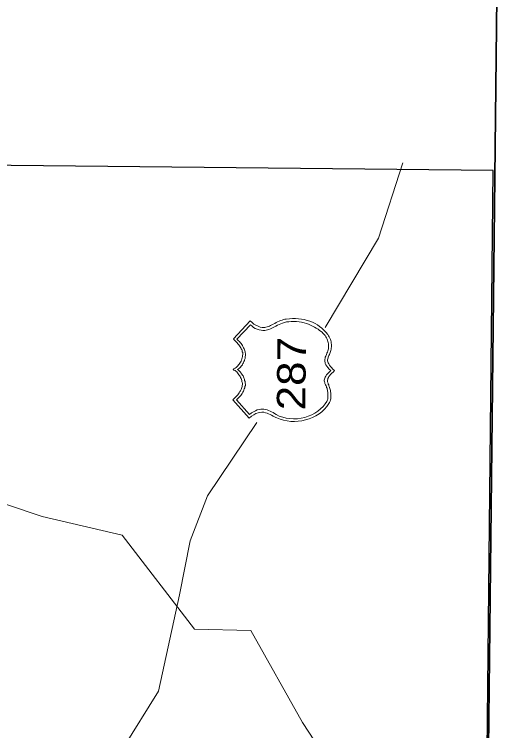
# Model space of a CAD drawing. Extents: x 2356576 to 2377878, y 6966390 to 6990634.
# Drawn here: x 2366109.4 to 2366226.3, y 6969120 to 6969290.7 of the extents above; entities that cross this region are included whole.
import ezdxf

# ---------------------------------------------------------------- set-up
doc = ezdxf.new("R2010")
doc.units = 0
doc.header["$LTSCALE"] = 7.1
doc.layers.add('19', color=7, linetype='Continuous', lineweight=13)
doc.layers.add('8', color=7, linetype='Continuous', lineweight=13)

msp = doc.modelspace()

# ---------------------------------------------------------------- linework, layer by layer
at = {"layer": '19', "lineweight": 35}
msp.add_line((2366217.375, 6968654.072), (2366226.339, 6969461.286), dxfattribs=at)
at = {"layer": '19'}
for p, q in [((2366202.034, 6969255.279), (2366196.264, 6969237.31)), ((2366196.264, 6969237.31), (2366183.535, 6969216.049)), ((2366155.514, 6969175.953), (2366167.219, 6969193.417))]:
    msp.add_line(p, q, dxfattribs=at)
at = {"layer": '19', "lineweight": 25}
msp.add_lwpolyline([(2365597.072, 6968660.498), (2366217.375, 6968654.072), (2366223.585, 6969253.468), (2365603.282, 6969259.894)], dxfattribs=at)
at = {"layer": '19'}
for points in [[(2366165.458, 6969194.423), (2366161.515, 6969198.816), (2366161.758, 6969199.053), (2366162.028, 6969199.291), (2366162.243, 6969199.556), (2366162.485, 6969199.766), (2366162.696, 6969200.032), (2366162.878, 6969200.27), (2366163.061, 6969200.508), (2366163.243, 6969200.778), (2366163.366, 6969200.985), (2366163.488, 6969201.256), (2366163.611, 6969201.494), (2366163.674, 6969201.762), (2366163.736, 6969202.001), (2366163.798, 6969202.212), (2366163.801, 6969202.512), (2366163.804, 6969202.78), (2366163.746, 6969202.961), (2366163.688, 6969203.174), (2366163.663, 6969203.414), (2366163.573, 6969203.655), (2366163.488, 6969203.896), (2366163.37, 6969204.105), (2366163.28, 6969204.346), (2366163.163, 6969204.587), (2366162.985, 6969204.801), (2366162.808, 6969205.043), (2366162.63, 6969205.253), (2366162.484, 6969205.466), (2366162.274, 6969205.616), (2366162.067, 6969205.799), (2366161.796, 6969205.893), (2366161.59, 6969206.043), (2366161.799, 6969206.193), (2366162.073, 6969206.339), (2366162.315, 6969206.516), (2366162.497, 6969206.694), (2366162.707, 6969206.904), (2366162.889, 6969207.142), (2366163.044, 6969207.349), (2366163.194, 6969207.587), (2366163.348, 6969207.825), (2366163.499, 6969208.036), (2366163.562, 6969208.335), (2366163.684, 6969208.542), (2366163.747, 6969208.873), (2366163.81, 6969209.081), (2366163.873, 6969209.38), (2366163.907, 6969209.62), (2366163.909, 6969209.832), (2366163.88, 6969210.1), (2366163.794, 6969210.281), (2366163.737, 6969210.554), (2366163.647, 6969210.794), (2366163.529, 6969211.004), (2366163.412, 6969211.217), (2366163.266, 6969211.486), (2366163.089, 6969211.7), (2366162.939, 6969211.942), (2366162.733, 6969212.152), (2366162.556, 6969212.426), (2366162.346, 6969212.636), (2366162.109, 6969212.878), (2366161.871, 6969213.093), (2366161.665, 6969213.335), (2366165.698, 6969217.642), (2366166.114, 6969217.249), (2366166.53, 6969216.853), (2366167.039, 6969216.58), (2366167.577, 6969216.362), (2366168.083, 6969216.149), (2366168.534, 6969216.052), (2366168.922, 6969216.048), (2366169.194, 6969216.045), (2366169.435, 6969216.103), (2366169.703, 6969216.192), (2366169.944, 6969216.278), (2366170.246, 6969216.394), (2366170.547, 6969216.543), (2366170.849, 6969216.688), (2366171.183, 6969216.865), (2366171.512, 6969217.041), (2366171.874, 6969217.218), (2366172.208, 6969217.394), (2366172.598, 6969217.542), (2366172.931, 6969217.687), (2366173.26, 6969217.803), (2366173.594, 6969217.92), (2366173.955, 6969218.008), (2366174.283, 6969218.065), (2366175.036, 6969218.145), (2366175.785, 6969218.229), (2366176.477, 6969218.222), (2366177.196, 6969218.122), (2366177.915, 6969218.055), (2366178.574, 6969217.928), (2366179.232, 6969217.741), (2366179.89, 6969217.527), (2366180.516, 6969217.308), (2366181.144, 6969217.002)], [(2366182.148, 6969215.403), (2366181.851, 6969215.674), (2366181.433, 6969215.918), (2366181.016, 6969216.163), (2366180.566, 6969216.407), (2366180.089, 6969216.624), (2366179.583, 6969216.838), (2366179.073, 6969217.023), (2366178.506, 6969217.181), (2366177.908, 6969217.335), (2366177.336, 6969217.401), (2366176.709, 6969217.499), (2366176.077, 6969217.506), (2366175.417, 6969217.481), (2366174.849, 6969217.427), (2366174.308, 6969217.372), (2366173.854, 6969217.229), (2366173.373, 6969217.114), (2366172.951, 6969216.938), (2366172.562, 6969216.79), (2366172.168, 6969216.614), (2366171.806, 6969216.41), (2366171.444, 6969216.202), (2366171.142, 6969216.025), (2366170.812, 6969215.88), (2366170.479, 6969215.732), (2366170.117, 6969215.588), (2366169.816, 6969215.499), (2366169.487, 6969215.414), (2366169.127, 6969215.358), (2366168.707, 6969215.33), (2366168.255, 6969215.427), (2366167.808, 6969215.52), (2366167.358, 6969215.644), (2366166.88, 6969215.829), (2366166.494, 6969216.073), (2366166.105, 6969216.377), (2366165.72, 6969216.681), (2366162.473, 6969213.295), (2366162.683, 6969213.085), (2366162.889, 6969212.902), (2366163.127, 6969212.688), (2366163.305, 6969212.478), (2366163.514, 6969212.236), (2366163.66, 6969211.994), (2366163.809, 6969211.753), (2366163.955, 6969211.511), (2366164.104, 6969211.238), (2366164.249, 6969210.996), (2366164.339, 6969210.727), (2366164.396, 6969210.487), (2366164.482, 6969210.246), (2366164.511, 6969210.033), (2366164.537, 6969209.825), (2366164.567, 6969209.613), (2366164.533, 6969209.405), (2366164.502, 6969209.165), (2366164.5, 6969208.894), (2366164.437, 6969208.686), (2366164.342, 6969208.387), (2366164.28, 6969208.176), (2366164.19, 6969207.937), (2366164.067, 6969207.67), (2366163.945, 6969207.459), (2366163.822, 6969207.192), (2366163.668, 6969207.014), (2366163.486, 6969206.804), (2366163.335, 6969206.565), (2366163.122, 6969206.388), (2366162.912, 6969206.21), (2366162.67, 6969206.032), (2366162.876, 6969205.85), (2366163.114, 6969205.668), (2366163.264, 6969205.486), (2366163.442, 6969205.304), (2366163.56, 6969205.095), (2366163.707, 6969204.942), (2366163.856, 6969204.7), (2366163.974, 6969204.519), (2366164.06, 6969204.31), (2366164.178, 6969204.069), (2366164.236, 6969203.888), (2366164.293, 6969203.647), (2366164.351, 6969203.435), (2366164.441, 6969203.226), (2366164.438, 6969202.986), (2366164.496, 6969202.773), (2366164.522, 6969202.565), (2366164.519, 6969202.265), (2366164.428, 6969201.994), (2366164.393, 6969201.694), (2366164.271, 6969201.455), (2366164.179, 6969201.156), (2366164.056, 6969200.858), (2366163.902, 6969200.651), (2366163.751, 6969200.353), (2366163.568, 6969200.083), (2366163.414, 6969199.844), (2366163.172, 6969199.639), (2366162.989, 6969199.369), (2366162.747, 6969199.163)], [(2366181.144, 6969217.002), (2366181.709, 6969216.668), (2366182.217, 6969216.27), (2366182.781, 6969215.905), (2366183.256, 6969215.392), (2366183.731, 6969214.935), (2366184.146, 6969214.39), (2366184.354, 6969214.088), (2366184.532, 6969213.818), (2366184.677, 6969213.517), (2366184.793, 6969213.216), (2366184.911, 6969212.942), (2366184.94, 6969212.642), (2366184.996, 6969212.313), (2366185.053, 6969212.041), (2366185.05, 6969211.713), (2366185.047, 6969211.413), (2366185.012, 6969211.141), (2366184.982, 6969210.901), (2366184.886, 6969210.602), (2366184.824, 6969210.363), (2366184.761, 6969210.124), (2366184.639, 6969209.885), (2366184.548, 6969209.646), (2366184.454, 6969209.407), (2366184.364, 6969209.228), (2366184.27, 6969208.989), (2366184.24, 6969208.809), (2366184.177, 6969208.57), (2366184.115, 6969208.33), (2366184.141, 6969208.122), (2366184.198, 6969207.881), (2366184.287, 6969207.608), (2366184.433, 6969207.367), (2366184.582, 6969207.097), (2366184.787, 6969206.795), (2366185.056, 6969206.492), (2366185.412, 6969206.157), (2366185.797, 6969205.793), (2366185.433, 6969205.436), (2366185.13, 6969205.14), (2366184.827, 6969204.875), (2366184.616, 6969204.577), (2366184.434, 6969204.367), (2366184.311, 6969204.128), (2366184.217, 6969203.921), (2366184.155, 6969203.71), (2366184.125, 6969203.53), (2366184.123, 6969203.322), (2366184.121, 6969203.142), (2366184.179, 6969202.929), (2366184.237, 6969202.781), (2366184.263, 6969202.568), (2366184.381, 6969202.359), (2366184.439, 6969202.179), (2366184.529, 6969201.998), (2366184.587, 6969201.785), (2366184.673, 6969201.544), (2366184.73, 6969201.276), (2366184.787, 6969201.035), (2366184.816, 6969200.763), (2366184.874, 6969200.494), (2366184.931, 6969200.253), (2366184.928, 6969199.953), (2366184.925, 6969199.681), (2366184.922, 6969199.413), (2366184.859, 6969199.082), (2366184.796, 6969198.815), (2366184.701, 6969198.516), (2366184.578, 6969198.217), (2366184.427, 6969197.918), (2366183.968, 6969197.231), (2366183.393, 6969196.577), (2366182.787, 6969195.955), (2366182.089, 6969195.451), (2366181.336, 6969194.978), (2366180.552, 6969194.598), (2366179.737, 6969194.307), (2366178.867, 6969194.044), (2366177.992, 6969193.845), (2366177.123, 6969193.734), (2366176.223, 6969193.683), (2366175.351, 6969193.692), (2366174.484, 6969193.789), (2366173.645, 6969193.95), (2366172.808, 6969194.199), (2366172.059, 6969194.506), (2366171.76, 6969194.63), (2366171.434, 6969194.781), (2366171.136, 6969194.964), (2366170.778, 6969195.148), (2366170.419, 6969195.331), (2366170.061, 6969195.515), (2366169.703, 6969195.671), (2366169.312, 6969195.763), (2366168.893, 6969195.859), (2366168.445, 6969195.864), (2366167.993, 6969195.837), (2366167.543, 6969195.721), (2366167.029, 6969195.547), (2366166.519, 6969195.284)], [(2366162.383, 6969198.807), (2366165.499, 6969195.354), (2366165.983, 6969195.709), (2366166.466, 6969196.004), (2366166.916, 6969196.208), (2366167.338, 6969196.415), (2366167.791, 6969196.499), (2366168.18, 6969196.587), (2366168.541, 6969196.611), (2366168.96, 6969196.579), (2366169.351, 6969196.483), (2366169.711, 6969196.419), (2366170.069, 6969196.295), (2366170.428, 6969196.111), (2366170.786, 6969195.96), (2366171.144, 6969195.776), (2366171.47, 6969195.561), (2366171.828, 6969195.349), (2366172.604, 6969194.949), (2366173.441, 6969194.672), (2366174.251, 6969194.452), (2366175.15, 6969194.354), (2366176.017, 6969194.313), (2366176.917, 6969194.336), (2366177.819, 6969194.475), (2366178.661, 6969194.646), (2366179.504, 6969194.909), (2366180.347, 6969195.261), (2366181.104, 6969195.673), (2366181.828, 6969196.113), (2366182.462, 6969196.647), (2366183.068, 6969197.213), (2366183.554, 6969197.836), (2366183.981, 6969198.463), (2366184.042, 6969198.611), (2366184.136, 6969198.79), (2366184.166, 6969199.001), (2366184.169, 6969199.241), (2366184.203, 6969199.421), (2366184.205, 6969199.661), (2366184.208, 6969199.901), (2366184.21, 6969200.141), (2366184.181, 6969200.409), (2366184.183, 6969200.621), (2366184.126, 6969200.89), (2366184.1, 6969201.13), (2366184.042, 6969201.343), (2366183.985, 6969201.583), (2366183.895, 6969201.792), (2366183.869, 6969201.972), (2366183.751, 6969202.154), (2366183.661, 6969202.367), (2366183.575, 6969202.516), (2366183.485, 6969202.729), (2366183.427, 6969202.937), (2366183.401, 6969203.117), (2366183.343, 6969203.33), (2366183.345, 6969203.538), (2366183.407, 6969203.749), (2366183.47, 6969204.017), (2366183.533, 6969204.256), (2366183.715, 6969204.494), (2366183.898, 6969204.792), (2366184.201, 6969205.089), (2366184.505, 6969205.446), (2366184.868, 6969205.774), (2366184.48, 6969206.166), (2366184.156, 6969206.53), (2366183.92, 6969206.864), (2366183.711, 6969207.194), (2366183.566, 6969207.468), (2366183.509, 6969207.737), (2366183.451, 6969207.977), (2366183.454, 6969208.277), (2366183.456, 6969208.489), (2366183.519, 6969208.696), (2366183.581, 6969208.968), (2366183.672, 6969209.207), (2366183.794, 6969209.414), (2366183.889, 6969209.653), (2366183.979, 6969209.924), (2366184.102, 6969210.191), (2366184.197, 6969210.462), (2366184.288, 6969210.729), (2366184.322, 6969211), (2366184.326, 6969211.3), (2366184.356, 6969211.568), (2366184.331, 6969211.868), (2366184.334, 6969212.14), (2366184.277, 6969212.441), (2366184.221, 6969212.741), (2366184.131, 6969213.01), (2366183.986, 6969213.312), (2366183.869, 6969213.585), (2366183.692, 6969213.855), (2366183.515, 6969214.157), (2366183.278, 6969214.399), (2366183.008, 6969214.674), (2366182.803, 6969214.916), (2366182.473, 6969215.16), (2366182.148, 6969215.403)], [(2366057.323, 6969199.743), (2366069.126, 6969192.209), (2366091.194, 6969179.379), (2366116.101, 6969171.021), (2366135.168, 6969166.623), (2366152.425, 6969144.183), (2366165.834, 6969143.864), (2366178.148, 6969121.955), (2366189.725, 6969104.283), (2366199.135, 6969082.764), (2366204.465, 6969052.823), (2366210.021, 6969027.324), (2366216.934, 6968999.531), (2366220.78, 6968982.778)], [(2366162.747, 6969199.163), (2366162.565, 6969198.985), (2366162.383, 6969198.807)], [(2366166.519, 6969195.284), (2366166.003, 6969194.929), (2366165.458, 6969194.423)], [(2366155.514, 6969175.953), (2366151.383, 6969165.227), (2366148.79, 6969152.413), (2366143.811, 6969129.392), (2366135.33, 6969115.799), (2366129.355, 6969106.648), (2366121.344, 6969094.85), (2366108.711, 6969083.249), (2366095.035, 6969075.202), (2366079.714, 6969067.44), (2366061.538, 6969056.344), (2366050.004, 6969046.563), (2366038.586, 6969039.093), (2366024.252, 6969030.869), (2366017.685, 6969025.629), (2366000.609, 6969016.381)]]:
    msp.add_lwpolyline(points, dxfattribs=at)
at = {"layer": '8', "lineweight": 35}
msp.add_line((2366217.375, 6968654.072), (2366226.339, 6969461.286), dxfattribs=at)
at = {"layer": '8'}
for p, q in [((2366202.034, 6969255.279), (2366196.264, 6969237.31)), ((2366196.264, 6969237.31), (2366183.535, 6969216.049)), ((2366155.514, 6969175.953), (2366167.219, 6969193.417))]:
    msp.add_line(p, q, dxfattribs=at)
at = {"layer": '8', "lineweight": 25}
msp.add_lwpolyline([(2365597.072, 6968660.498), (2366217.375, 6968654.072), (2366223.585, 6969253.468), (2365603.282, 6969259.894)], dxfattribs=at)
at = {"layer": '8'}
for points in [[(2366165.458, 6969194.423), (2366161.515, 6969198.816), (2366161.758, 6969199.053), (2366162.028, 6969199.291), (2366162.243, 6969199.556), (2366162.485, 6969199.766), (2366162.696, 6969200.032), (2366162.878, 6969200.27), (2366163.061, 6969200.508), (2366163.243, 6969200.778), (2366163.366, 6969200.985), (2366163.488, 6969201.256), (2366163.611, 6969201.494), (2366163.674, 6969201.762), (2366163.736, 6969202.001), (2366163.798, 6969202.212), (2366163.801, 6969202.512), (2366163.804, 6969202.78), (2366163.746, 6969202.961), (2366163.688, 6969203.174), (2366163.663, 6969203.414), (2366163.573, 6969203.655), (2366163.488, 6969203.896), (2366163.37, 6969204.105), (2366163.28, 6969204.346), (2366163.163, 6969204.587), (2366162.985, 6969204.801), (2366162.808, 6969205.043), (2366162.63, 6969205.253), (2366162.484, 6969205.466), (2366162.274, 6969205.616), (2366162.067, 6969205.799), (2366161.796, 6969205.893), (2366161.59, 6969206.043), (2366161.799, 6969206.193), (2366162.073, 6969206.339), (2366162.315, 6969206.516), (2366162.497, 6969206.694), (2366162.707, 6969206.904), (2366162.889, 6969207.142), (2366163.044, 6969207.349), (2366163.194, 6969207.587), (2366163.348, 6969207.825), (2366163.499, 6969208.036), (2366163.562, 6969208.335), (2366163.684, 6969208.542), (2366163.747, 6969208.873), (2366163.81, 6969209.081), (2366163.873, 6969209.38), (2366163.907, 6969209.62), (2366163.909, 6969209.832), (2366163.88, 6969210.1), (2366163.794, 6969210.281), (2366163.737, 6969210.554), (2366163.647, 6969210.794), (2366163.529, 6969211.004), (2366163.412, 6969211.217), (2366163.266, 6969211.486), (2366163.089, 6969211.7), (2366162.939, 6969211.942), (2366162.733, 6969212.152), (2366162.556, 6969212.426), (2366162.346, 6969212.636), (2366162.109, 6969212.878), (2366161.871, 6969213.093), (2366161.665, 6969213.335), (2366165.698, 6969217.642), (2366166.114, 6969217.249), (2366166.53, 6969216.853), (2366167.039, 6969216.58), (2366167.577, 6969216.362), (2366168.083, 6969216.149), (2366168.534, 6969216.052), (2366168.922, 6969216.048), (2366169.194, 6969216.045), (2366169.435, 6969216.103), (2366169.703, 6969216.192), (2366169.944, 6969216.278), (2366170.246, 6969216.394), (2366170.547, 6969216.543), (2366170.849, 6969216.688), (2366171.183, 6969216.865), (2366171.512, 6969217.041), (2366171.874, 6969217.218), (2366172.208, 6969217.394), (2366172.598, 6969217.542), (2366172.931, 6969217.687), (2366173.26, 6969217.803), (2366173.594, 6969217.92), (2366173.955, 6969218.008), (2366174.283, 6969218.065), (2366175.036, 6969218.145), (2366175.785, 6969218.229), (2366176.477, 6969218.222), (2366177.196, 6969218.122), (2366177.915, 6969218.055), (2366178.574, 6969217.928), (2366179.232, 6969217.741), (2366179.89, 6969217.527), (2366180.516, 6969217.308), (2366181.144, 6969217.002)], [(2366182.148, 6969215.403), (2366181.851, 6969215.674), (2366181.433, 6969215.918), (2366181.016, 6969216.163), (2366180.566, 6969216.407), (2366180.089, 6969216.624), (2366179.583, 6969216.838), (2366179.073, 6969217.023), (2366178.506, 6969217.181), (2366177.908, 6969217.335), (2366177.336, 6969217.401), (2366176.709, 6969217.499), (2366176.077, 6969217.506), (2366175.417, 6969217.481), (2366174.849, 6969217.427), (2366174.308, 6969217.372), (2366173.854, 6969217.229), (2366173.373, 6969217.114), (2366172.951, 6969216.938), (2366172.562, 6969216.79), (2366172.168, 6969216.614), (2366171.806, 6969216.41), (2366171.444, 6969216.202), (2366171.142, 6969216.025), (2366170.812, 6969215.88), (2366170.479, 6969215.732), (2366170.117, 6969215.588), (2366169.816, 6969215.499), (2366169.487, 6969215.414), (2366169.127, 6969215.358), (2366168.707, 6969215.33), (2366168.255, 6969215.427), (2366167.808, 6969215.52), (2366167.358, 6969215.644), (2366166.88, 6969215.829), (2366166.494, 6969216.073), (2366166.105, 6969216.377), (2366165.72, 6969216.681), (2366162.473, 6969213.295), (2366162.683, 6969213.085), (2366162.889, 6969212.902), (2366163.127, 6969212.688), (2366163.305, 6969212.478), (2366163.514, 6969212.236), (2366163.66, 6969211.994), (2366163.809, 6969211.753), (2366163.955, 6969211.511), (2366164.104, 6969211.238), (2366164.249, 6969210.996), (2366164.339, 6969210.727), (2366164.396, 6969210.487), (2366164.482, 6969210.246), (2366164.511, 6969210.033), (2366164.537, 6969209.825), (2366164.567, 6969209.613), (2366164.533, 6969209.405), (2366164.502, 6969209.165), (2366164.5, 6969208.894), (2366164.437, 6969208.686), (2366164.342, 6969208.387), (2366164.28, 6969208.176), (2366164.19, 6969207.937), (2366164.067, 6969207.67), (2366163.945, 6969207.459), (2366163.822, 6969207.192), (2366163.668, 6969207.014), (2366163.486, 6969206.804), (2366163.335, 6969206.565), (2366163.122, 6969206.388), (2366162.912, 6969206.21), (2366162.67, 6969206.032), (2366162.876, 6969205.85), (2366163.114, 6969205.668), (2366163.264, 6969205.486), (2366163.442, 6969205.304), (2366163.56, 6969205.095), (2366163.707, 6969204.942), (2366163.856, 6969204.7), (2366163.974, 6969204.519), (2366164.06, 6969204.31), (2366164.178, 6969204.069), (2366164.236, 6969203.888), (2366164.293, 6969203.647), (2366164.351, 6969203.435), (2366164.441, 6969203.226), (2366164.438, 6969202.986), (2366164.496, 6969202.773), (2366164.522, 6969202.565), (2366164.519, 6969202.265), (2366164.428, 6969201.994), (2366164.393, 6969201.694), (2366164.271, 6969201.455), (2366164.179, 6969201.156), (2366164.056, 6969200.858), (2366163.902, 6969200.651), (2366163.751, 6969200.353), (2366163.568, 6969200.083), (2366163.414, 6969199.844), (2366163.172, 6969199.639), (2366162.989, 6969199.369), (2366162.747, 6969199.163)], [(2366181.144, 6969217.002), (2366181.709, 6969216.668), (2366182.217, 6969216.27), (2366182.781, 6969215.905), (2366183.256, 6969215.392), (2366183.731, 6969214.935), (2366184.146, 6969214.39), (2366184.354, 6969214.088), (2366184.532, 6969213.818), (2366184.677, 6969213.517), (2366184.793, 6969213.216), (2366184.911, 6969212.942), (2366184.94, 6969212.642), (2366184.996, 6969212.313), (2366185.053, 6969212.041), (2366185.05, 6969211.713), (2366185.047, 6969211.413), (2366185.012, 6969211.141), (2366184.982, 6969210.901), (2366184.886, 6969210.602), (2366184.824, 6969210.363), (2366184.761, 6969210.124), (2366184.639, 6969209.885), (2366184.548, 6969209.646), (2366184.454, 6969209.407), (2366184.364, 6969209.228), (2366184.27, 6969208.989), (2366184.24, 6969208.809), (2366184.177, 6969208.57), (2366184.115, 6969208.33), (2366184.141, 6969208.122), (2366184.198, 6969207.881), (2366184.287, 6969207.608), (2366184.433, 6969207.367), (2366184.582, 6969207.097), (2366184.787, 6969206.795), (2366185.056, 6969206.492), (2366185.412, 6969206.157), (2366185.797, 6969205.793), (2366185.433, 6969205.436), (2366185.13, 6969205.14), (2366184.827, 6969204.875), (2366184.616, 6969204.577), (2366184.434, 6969204.367), (2366184.311, 6969204.128), (2366184.217, 6969203.921), (2366184.155, 6969203.71), (2366184.125, 6969203.53), (2366184.123, 6969203.322), (2366184.121, 6969203.142), (2366184.179, 6969202.929), (2366184.237, 6969202.781), (2366184.263, 6969202.568), (2366184.381, 6969202.359), (2366184.439, 6969202.179), (2366184.529, 6969201.998), (2366184.587, 6969201.785), (2366184.673, 6969201.544), (2366184.73, 6969201.276), (2366184.787, 6969201.035), (2366184.816, 6969200.763), (2366184.874, 6969200.494), (2366184.931, 6969200.253), (2366184.928, 6969199.953), (2366184.925, 6969199.681), (2366184.922, 6969199.413), (2366184.859, 6969199.082), (2366184.796, 6969198.815), (2366184.701, 6969198.516), (2366184.578, 6969198.217), (2366184.427, 6969197.918), (2366183.968, 6969197.231), (2366183.393, 6969196.577), (2366182.787, 6969195.955), (2366182.089, 6969195.451), (2366181.336, 6969194.978), (2366180.552, 6969194.598), (2366179.737, 6969194.307), (2366178.867, 6969194.044), (2366177.992, 6969193.845), (2366177.123, 6969193.734), (2366176.223, 6969193.683), (2366175.351, 6969193.692), (2366174.484, 6969193.789), (2366173.645, 6969193.95), (2366172.808, 6969194.199), (2366172.059, 6969194.506), (2366171.76, 6969194.63), (2366171.434, 6969194.781), (2366171.136, 6969194.964), (2366170.778, 6969195.148), (2366170.419, 6969195.331), (2366170.061, 6969195.515), (2366169.703, 6969195.671), (2366169.312, 6969195.763), (2366168.893, 6969195.859), (2366168.445, 6969195.864), (2366167.993, 6969195.837), (2366167.543, 6969195.721), (2366167.029, 6969195.547), (2366166.519, 6969195.284)], [(2366162.383, 6969198.807), (2366165.499, 6969195.354), (2366165.983, 6969195.709), (2366166.466, 6969196.004), (2366166.916, 6969196.208), (2366167.338, 6969196.415), (2366167.791, 6969196.499), (2366168.18, 6969196.587), (2366168.541, 6969196.611), (2366168.96, 6969196.579), (2366169.351, 6969196.483), (2366169.711, 6969196.419), (2366170.069, 6969196.295), (2366170.428, 6969196.111), (2366170.786, 6969195.96), (2366171.144, 6969195.776), (2366171.47, 6969195.561), (2366171.828, 6969195.349), (2366172.604, 6969194.949), (2366173.441, 6969194.672), (2366174.251, 6969194.452), (2366175.15, 6969194.354), (2366176.017, 6969194.313), (2366176.917, 6969194.336), (2366177.819, 6969194.475), (2366178.661, 6969194.646), (2366179.504, 6969194.909), (2366180.347, 6969195.261), (2366181.104, 6969195.673), (2366181.828, 6969196.113), (2366182.462, 6969196.647), (2366183.068, 6969197.213), (2366183.554, 6969197.836), (2366183.981, 6969198.463), (2366184.042, 6969198.611), (2366184.136, 6969198.79), (2366184.166, 6969199.001), (2366184.169, 6969199.241), (2366184.203, 6969199.421), (2366184.205, 6969199.661), (2366184.208, 6969199.901), (2366184.21, 6969200.141), (2366184.181, 6969200.409), (2366184.183, 6969200.621), (2366184.126, 6969200.89), (2366184.1, 6969201.13), (2366184.042, 6969201.343), (2366183.985, 6969201.583), (2366183.895, 6969201.792), (2366183.869, 6969201.972), (2366183.751, 6969202.154), (2366183.661, 6969202.367), (2366183.575, 6969202.516), (2366183.485, 6969202.729), (2366183.427, 6969202.937), (2366183.401, 6969203.117), (2366183.343, 6969203.33), (2366183.345, 6969203.538), (2366183.407, 6969203.749), (2366183.47, 6969204.017), (2366183.533, 6969204.256), (2366183.715, 6969204.494), (2366183.898, 6969204.792), (2366184.201, 6969205.089), (2366184.505, 6969205.446), (2366184.868, 6969205.774), (2366184.48, 6969206.166), (2366184.156, 6969206.53), (2366183.92, 6969206.864), (2366183.711, 6969207.194), (2366183.566, 6969207.468), (2366183.509, 6969207.737), (2366183.451, 6969207.977), (2366183.454, 6969208.277), (2366183.456, 6969208.489), (2366183.519, 6969208.696), (2366183.581, 6969208.968), (2366183.672, 6969209.207), (2366183.794, 6969209.414), (2366183.889, 6969209.653), (2366183.979, 6969209.924), (2366184.102, 6969210.191), (2366184.197, 6969210.462), (2366184.288, 6969210.729), (2366184.322, 6969211), (2366184.326, 6969211.3), (2366184.356, 6969211.568), (2366184.331, 6969211.868), (2366184.334, 6969212.14), (2366184.277, 6969212.441), (2366184.221, 6969212.741), (2366184.131, 6969213.01), (2366183.986, 6969213.312), (2366183.869, 6969213.585), (2366183.692, 6969213.855), (2366183.515, 6969214.157), (2366183.278, 6969214.399), (2366183.008, 6969214.674), (2366182.803, 6969214.916), (2366182.473, 6969215.16), (2366182.148, 6969215.403)], [(2366057.323, 6969199.743), (2366069.126, 6969192.209), (2366091.194, 6969179.379), (2366116.101, 6969171.021), (2366135.168, 6969166.623), (2366152.425, 6969144.183), (2366165.834, 6969143.864), (2366178.148, 6969121.955), (2366189.725, 6969104.283), (2366199.135, 6969082.764), (2366204.465, 6969052.823), (2366210.021, 6969027.324), (2366216.934, 6968999.531), (2366220.78, 6968982.778)], [(2366162.747, 6969199.163), (2366162.565, 6969198.985), (2366162.383, 6969198.807)], [(2366166.519, 6969195.284), (2366166.003, 6969194.929), (2366165.458, 6969194.423)], [(2366155.514, 6969175.953), (2366151.383, 6969165.227), (2366148.79, 6969152.413), (2366143.811, 6969129.392), (2366135.33, 6969115.799), (2366129.355, 6969106.648), (2366121.344, 6969094.85), (2366108.711, 6969083.249), (2366095.035, 6969075.202), (2366079.714, 6969067.44), (2366061.538, 6969056.344), (2366050.004, 6969046.563), (2366038.586, 6969039.093), (2366024.252, 6969030.869), (2366017.685, 6969025.629), (2366000.609, 6969016.381)]]:
    msp.add_lwpolyline(points, dxfattribs=at)

# ---------------------------------------------------------------- texts
at = {"layer": '19', "width": 1.15}
msp.add_text('287', height=6.798, rotation=89.406, dxfattribs=at).set_placement((2366178.798, 6969196.297))
at = {"layer": '8', "width": 1.15}
msp.add_text('287', height=6.798, rotation=89.406, dxfattribs=at).set_placement((2366178.798, 6969196.297))

doc.saveas('drawing.dxf')
